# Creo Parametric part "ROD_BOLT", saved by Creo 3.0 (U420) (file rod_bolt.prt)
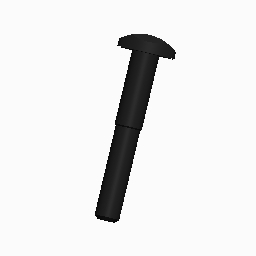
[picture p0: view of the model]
Units: millimeter Kilogram Sec (mmKs); MM, KILOGRAM, SECS

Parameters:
  MATERIAL = "35CrMo"

Created from: INLBS_PART_SOLID.PRT

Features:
  1. datum plane "SIDE", "RIGHT"
  2. datum plane "DTM1", "TOP"
  3. datum plane "DTM2", "FRONT"
  4. coordinate system "ORIGIN"
  5. revolve "Revolve 1"
  6. extrusion "Extrude 1"
  7. extruded cut "Extrude 2"
  8. extruded cut "Extrude 3"
  9. chamfer "Chamfer 1"
  10. datum point "CON_WELD"
  11. round "Round id 160"

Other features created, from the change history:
  group "COPIED_GROUP"

Surfaces: 9 cylinder, 8 plane, 4 cone, 4 torus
